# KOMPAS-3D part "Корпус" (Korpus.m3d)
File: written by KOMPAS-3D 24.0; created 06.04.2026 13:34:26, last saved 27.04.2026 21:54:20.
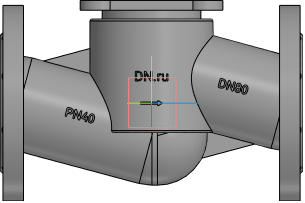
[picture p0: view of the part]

Document properties: Автор: R2D2; Полное имя файла: C:\Работа\ГОТОВЫЕ ИСХОДНИКИ\VSO2130M-F-S Клапан запорный сальниковый DN.ru Ду15-100 Ру40\исходные материалы\DN80\Korpus.m3d

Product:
- Body: Труба / Нестандартная труба / L = 199.9 мм  | qty 1  | 2 such rows
    Материал: Нестандартная труба (density 7856 kg/m3)
    Масса: 33.847386
    Раздел спецификации: Детали
    Примечание: 11,37 кг
    additional columns: Pipeline; 0.096; 0; 0; 0.002; 0.19992; true; 0.04
- Body: Тело 4  | qty 1
    Материал: Нестандартная труба (density 7856 kg/m3)
    Масса: 33.847386
- Body: Тело 5  | qty 1
    Материал: Нестандартная труба (density 7856 kg/m3)
    Масса: 33.847386
- Body: Тело 8  | qty 1
    Материал: Нестандартная труба (density 7856 kg/m3)
    Масса: 33.847386
- Body: Тело 10  | qty 1
    Материал: Нестандартная труба (density 7856 kg/m3)
    Масса: 33.847386
- Body: Тело 11  | qty 1
    Материал: Нестандартная труба (density 7856 kg/m3)
    Масса: 33.847386
- Body: Тело 12  | qty 1
    Материал: Нестандартная труба (density 7856 kg/m3)
    Масса: 33.847386
- Body: Тело 13  | qty 1
    Материал: Нестандартная труба (density 7856 kg/m3)
    Масса: 33.847386
- Body: Тело 14  | qty 1
    Материал: Нестандартная труба (density 7856 kg/m3)
    Масса: 33.847386
- Body: Тело 15  | qty 1
    Материал: Нестандартная труба (density 7856 kg/m3)
    Масса: 33.847386
- Part/product: Корпус
    Масса: 6.9

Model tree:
1. Труба:1  (labels: {F703FF30-5BE6-4673-A7F1-8EDA1BE1E2D1}; SHAPEOBJECT3D_ATTR_BUTT; SHAPEOBJECT3D_ATTR_VALID; SHAPEOBJECT3D_ATTR_BUTT_AREA)
     PIPE_R = 3
2. Труба:2  (labels: {F703FF30-5BE6-4673-A7F1-8EDA1BE1E2D1}; SHAPEOBJECT3D_ATTR_BUTT; SHAPEOBJECT3D_ATTR_VALID; SHAPEOBJECT3D_ATTR_BUTT_AREA)
     PIPE_R = 3
3. Колонна
4. Элемент выдавливания:1
     Смещение 1 = -1; Смещение 2 = -5
5. Скругление:17  (with: Ребро.Элемент выдавливания:1)
     Радиус = 2
6. Скругление:18  (with: Ребро.Элемент выдавливания:1)
7. Скругление:24
     Радиус = 1.5
8. Элемент выдавливания:2
     Расстояние 1 = 6
9. Эскиз:4  (with: Грань.Элемент выдавливания:1)
10. Элемент выдавливания:3
     Расстояние 1 = 9
11. ОТЛИВКА
12. Скругление:6  (with: Грань.Элемент выдавливания:1)
     Радиус = 2
13. Элемент выдавливания:6  (with: Грань.Элемент выдавливания:1)
     Смещение 1 = 4
14. ЛЕЙБЛ
15. Элемент выдавливания:7  (with: Грань.Элемент выдавливания:1)
     Расстояние 1 = 63.9692; Смещение 1 = 1
16. Dn
17. Pn
18. Стрелочка
19. Элемент выдавливания:10  (with: Грань.Труба:1)
     Расстояние 1 = 48.8977; Смещение 1 = 1
20. Элемент выдавливания:11  (with: Грань.Труба:2)
     Расстояние 1 = 48.8176; Смещение 1 = 1
21. Элемент выдавливания:12  (with: Грань.Элемент выдавливания:1)
     Расстояние 1 = 63.9997; Смещение 1 = 1
22. Материал
23. Элемент выдавливания:13  (with: Грань.Элемент выдавливания:1)
     Расстояние 1 = 63.4915; Смещение 1 = 0.5
24. Фланец верх  (with: Грань.Элемент выдавливания:3)
25. Элемент выдавливания:14
     Расстояние 1 = 10
26. Эскиз:18  (with: Грань.Элемент выдавливания:14)
27. Элемент выдавливания:15
     Расстояние 1 = 0.5
28. Эскиз:19  (with: Грань.Элемент выдавливания:14, Ребро.Элемент выдавливания:14)
29. Элемент выдавливания:16  (with: Грань.Элемент выдавливания:14)
     Расстояние 1 = 0.5; Расстояние 2 = 11; Смещение 2 = 1
30. Массив по сетке:1  (with: Элемент выдавливания:16, Эскиз:19)  (4 pattern instances)
     Угол раствора = 90
31. Фланец
32. Элемент вращения:1
     Угол 1 = 360
33. отвертие во фланце  (with: Грань.Элемент вращения:1)
34. Элемент выдавливания:8
35. Массив по концентрической сетке:2  (with: Элемент выдавливания:8, Эскиз:10, Грань.Элемент вращения:1)  (8 pattern instances)
     Шаг 2 = 360
36. Зеркальный массив:1
37. Экземпляр ( 1 )
38. Экземпляр ( 2 )  (with: Элемент вращения:1, Массив по концентрической сетке:2, Экземпляр ( 1 ), Элемент выдавливания:8)
39. Экземпляр ( 3 )  (with: Элемент выдавливания:8)
40. Экземпляр ( 4 )  (with: Элемент выдавливания:8)
41. Экземпляр ( 5 )  (with: Элемент выдавливания:8)
42. Экземпляр ( 6 )  (with: Элемент выдавливания:8)
43. Экземпляр ( 7 )  (with: Элемент выдавливания:8)
44. Экземпляр ( 8 )  (with: Элемент выдавливания:8)
45. Скругление:25  (with: Ребро.Элемент выдавливания:1)
     Радиус = 2

Expressions: DS/2+3; LL/2; DN/2; D1/2+15; A/3+DN; D2/2-15; D2-15*2
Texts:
  GOST 26.020 Pr3
  var3D
  GS-C25
  смещение колонны вниз
  LL-10
  DN+20
  DS+25
  nd+20
  Труба / Нестандартная труба / L = %s мм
